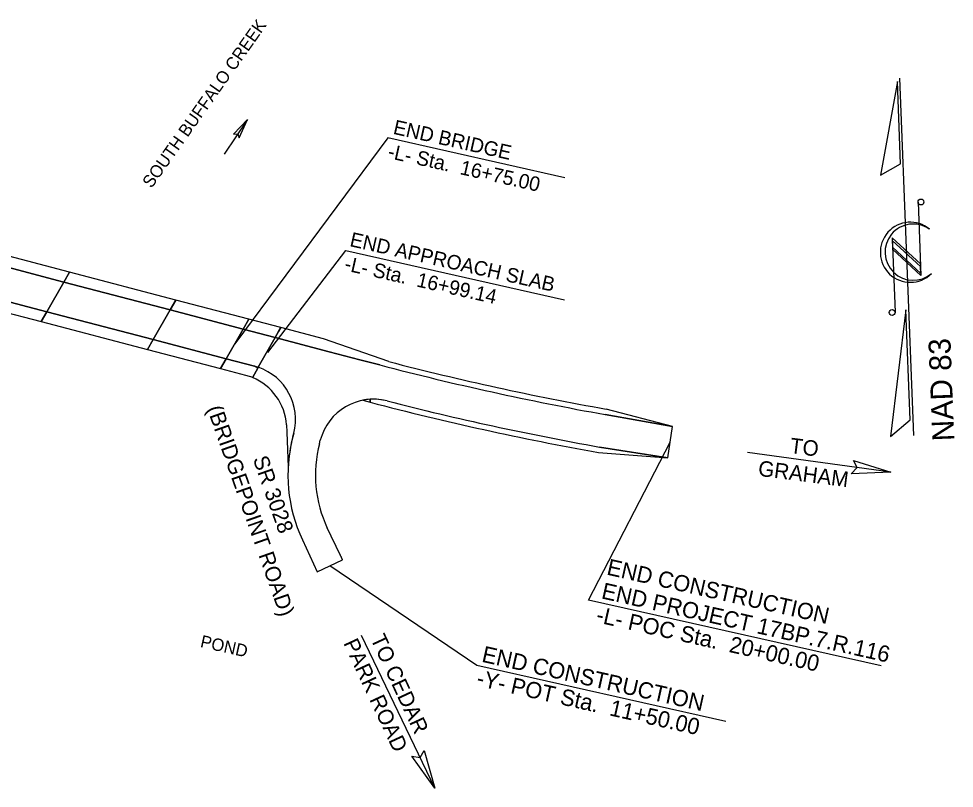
# Model space of a CAD drawing. Extents: x 1784499 to 1786147, y 841097 to 842538.
# Drawn here: x 1785466 to 1786147, y 841097 to 841656 of the extents above; entities that cross this region are included whole.
import ezdxf

# ---------------------------------------------------------------- set-up
doc = ezdxf.new("R2010")
doc.units = 0
for name, color, linetype in [('Exist Hydro Stream or Body of Water Text', 7, 'Continuous'), ('Exist Roads EOP Text', 7, 'Continuous'), ('Prop DSN Text', 7, 'Continuous'), ('Prop Horizontal Alignment Station Label', 7, 'Continuous'), ('Prop Leader Line Medium', 7, 'Continuous'), ('Prop Shade Light', 7, 'Continuous'), ('Prop Terminator CELL', 7, 'Continuous'), ('Sheet North Arrow CELL', 7, 'Continuous')]:
    doc.layers.add(name, color=color, linetype=linetype)

msp = doc.modelspace()

# ---------------------------------------------------------------- linework, layer by layer
at = {"layer": 'Prop DSN Text'}
for p, q in [((1785735.02, 841569.71), (1785623.67, 841419.93)), ((1785863.87, 841540.82), (1785735.02, 841569.71)), ((1785647.85, 841413.6), (1785704.42, 841487.83)), ((1785704.42, 841487.83), (1785863.65, 841452.12))]:
    msp.add_line(p, q, dxfattribs=at)
at = {"layer": 'Prop Horizontal Alignment Station Label'}
for p, q in [((1785881.09, 841233.67), (1785940.53, 841348.54)), ((1785799.79, 841186.08), (1785692.94, 841258.65)), ((1786094.14, 841185.89), (1785881.09, 841233.67)), ((1785980.91, 841145.46), (1785799.79, 841186.08))]:
    msp.add_line(p, q, dxfattribs=at)
at = {"layer": 'Prop Leader Line Medium'}
for p, q in [((1785632.85, 841583.2), (1785616.01, 841557.96)), ((1786101.01, 841326.66), (1785996.85, 841340.92)), ((1785769.21, 841096.81), (1785715.99, 841207.96))]:
    msp.add_line(p, q, dxfattribs=at)
at = {"layer": 'Prop Shade Light'}
for p, q in [((1785503.33, 841472.15), (1785450.13, 841486.09)), ((1785499.23, 841464.95), (1785446.03, 841478.89)), ((1785446.03, 841478.89), (1785499.23, 841464.95)), ((1785499.23, 841464.95), (1785503.33, 841472.15)), ((1785503.33, 841472.15), (1785499.23, 841464.95)), ((1785580.72, 841451.87), (1785503.33, 841472.15)), ((1785486.92, 841443.36), (1785499.23, 841464.95)), ((1785499.23, 841464.95), (1785486.92, 841443.36)), ((1785576.62, 841444.67), (1785499.23, 841464.95)), ((1785499.23, 841464.95), (1785576.62, 841444.67)), ((1785433.72, 841457.31), (1785486.92, 841443.36)), ((1785486.92, 841443.36), (1785433.72, 841457.31)), ((1785576.62, 841444.67), (1785580.72, 841451.87)), ((1785580.72, 841451.87), (1785576.62, 841444.67)), ((1785633.92, 841437.92), (1785580.72, 841451.87)), ((1785429.62, 841450.11), (1785482.82, 841436.17)), ((1785482.82, 841436.17), (1785486.92, 841443.36)), ((1785486.92, 841443.36), (1785482.82, 841436.17)), ((1785486.92, 841443.36), (1785564.31, 841423.08)), ((1785564.31, 841423.08), (1785486.92, 841443.36)), ((1785564.31, 841423.08), (1785576.62, 841444.67)), ((1785576.62, 841444.67), (1785564.31, 841423.08)), ((1785576.62, 841444.67), (1785629.82, 841430.73)), ((1785629.82, 841430.73), (1785576.62, 841444.67)), ((1785629.82, 841430.73), (1785633.92, 841437.92)), ((1785633.92, 841437.92), (1785629.82, 841430.73)), ((1785657.27, 841431.8), (1785633.92, 841437.92)), ((1785482.82, 841436.17), (1785560.21, 841415.89)), ((1785617.51, 841409.14), (1785629.82, 841430.73)), ((1785629.82, 841430.73), (1785617.51, 841409.14)), ((1785653.17, 841424.61), (1785629.82, 841430.73)), ((1785629.82, 841430.73), (1785653.17, 841424.61)), ((1785655.6, 841428.87), (1785657.27, 841431.8)), ((1785657.27, 841431.8), (1785655.6, 841428.87)), ((1785688.33, 841423.66), (1785657.27, 841431.8)), ((1785560.21, 841415.89), (1785564.31, 841423.08)), ((1785564.31, 841423.08), (1785560.21, 841415.89)), ((1785564.31, 841423.08), (1785617.51, 841409.14)), ((1785617.51, 841409.14), (1785564.31, 841423.08)), ((1785640.81, 841402.93), (1785653.17, 841424.61)), ((1785653.17, 841424.61), (1785640.81, 841402.93)), ((1785653.17, 841424.61), (1785655.6, 841428.87)), ((1785655.6, 841428.87), (1785653.17, 841424.61)), ((1785692.49, 841414.3), (1785653.17, 841424.61)), ((1785653.17, 841424.61), (1785692.49, 841414.3)), ((1785735.74, 841407.11), (1785688.33, 841423.66)), ((1785560.21, 841415.89), (1785613.41, 841401.95)), ((1785714.74, 841408.47), (1785692.49, 841414.3)), ((1785692.49, 841414.3), (1785714.74, 841408.47)), ((1785613.41, 841401.95), (1785617.51, 841409.14)), ((1785617.51, 841409.14), (1785613.41, 841401.95)), ((1785638.04, 841403.76), (1785617.51, 841409.14)), ((1785617.51, 841409.14), (1785638.04, 841403.76)), ((1785729.33, 841404.65), (1785714.74, 841408.47)), ((1785714.74, 841408.47), (1785729.33, 841404.65)), ((1785613.41, 841401.95), (1785631.55, 841397.19)), ((1785631.55, 841397.19), (1785636.76, 841395.83)), ((1785716.83, 841378.98), (1785722.23, 841377.57)), ((1785942.29, 841359.92), (1785893.32, 841368.57)), ((1785893.32, 841368.57), (1785942.29, 841359.92)), ((1785942.29, 841359.92), (1785894.03, 841372.51)), ((1785661.33, 841361.08), (1785661.67, 841355.83)), ((1785661.67, 841355.83), (1785662.5, 841330.27)), ((1785666.59, 841354.93), (1785665.95, 841352.47)), ((1785665.95, 841352.47), (1785666.59, 841354.93)), ((1785938.76, 841337.04), (1785942.29, 841359.92)), ((1785685.29, 841347.4), (1785685.95, 841349.89)), ((1785889.1, 841344.94), (1785938.76, 841337.04)), ((1785938.76, 841337.04), (1785889.1, 841344.94)), ((1785888.4, 841341.01), (1785938.76, 841337.04)), ((1785691.27, 841285.52), (1785691.02, 841286.06)), ((1785672.94, 841277.5), (1785683.59, 841254.22)), ((1785683.59, 841254.22), (1785702.17, 841263.02))]:
    msp.add_line(p, q, dxfattribs=at)
for points in [[(1785640.81, 841402.93), (1785640.49, 841402.36), (1785639.25, 841400.18), (1785636.76, 841395.83)], [(1785640.49, 841402.36), (1785638.04, 841403.76)], [(1785636.76, 841395.83), (1785636.63, 841395.49)], [(1785636.76, 841395.83), (1785639.25, 841400.18), (1785640.49, 841402.36)], [(1785722.1, 841379.67), (1785722.23, 841377.56)], [(1785722.23, 841377.57), (1785722.1, 841379.67)]]:
    msp.add_lwpolyline(points, dxfattribs=at)
for centre, radius, start, end in [((1785627.9, 841365.07), 40, 71.16248, 75.31501), ((1785627.9, 841365.07), 40, 345.31501, 71.16248), ((1785627.9, 841365.07), 40, 345.31501, 71.16248), ((1786264.98, 843448.63), 2113, 255.31501, 259.86941), ((1786264.98, 843448.63), 2113, 255.31501, 259.86941), ((1786264.98, 843448.63), 2109, 255.46645, 259.86941), ((1785621.41, 841358.5), 40, 3.69528, 67.64057), ((1785724.64, 841339.75), 40, 75.6286, 165.31501), ((1785724.64, 841339.75), 40, 93.64367, 101.25487), ((1785724.64, 841339.75), 40, 75.6286, 93.64367), ((1786264.98, 843448.63), 2141, 255.31501, 259.86941), ((1786264.98, 843448.63), 2137, 255.6286, 259.86941), ((1786264.98, 843448.63), 2137, 255.6286, 259.86941), ((1785772.35, 841324.59), 110, 165.31501, 205.34637), ((1785772.35, 841324.59), 110, 165.31501, 177.03762), ((1785772.35, 841324.59), 90, 165.31501, 205.34637)]:
    msp.add_arc(centre, radius, start, end, dxfattribs=at)
for points in [[(1785694.9, 841278.02), (1785694.87, 841278.09), (1785694.84, 841278.16), (1785694.8, 841278.23), (1785694.76, 841278.33), (1785694.71, 841278.43), (1785694.66, 841278.53), (1785694.61, 841278.63), (1785694.56, 841278.73), (1785694.51, 841278.83), (1785694.46, 841278.94), (1785694.41, 841279.04), (1785694.36, 841279.14), (1785694.31, 841279.24), (1785694.26, 841279.34), (1785694.22, 841279.44), (1785694.17, 841279.54), (1785694.12, 841279.65), (1785694.07, 841279.75), (1785694.02, 841279.85), (1785693.97, 841279.95), (1785693.92, 841280.05), (1785693.87, 841280.15), (1785693.82, 841280.25), (1785693.77, 841280.35), (1785693.72, 841280.46), (1785693.68, 841280.56), (1785693.63, 841280.66), (1785693.58, 841280.76), (1785693.53, 841280.86), (1785693.48, 841280.96), (1785693.43, 841281.06), (1785693.38, 841281.17), (1785693.33, 841281.27), (1785693.28, 841281.37), (1785693.23, 841281.47), (1785693.18, 841281.57), (1785693.14, 841281.67), (1785693.09, 841281.77), (1785693.04, 841281.88), (1785692.99, 841281.98), (1785692.94, 841282.08), (1785692.89, 841282.18), (1785692.84, 841282.28), (1785692.79, 841282.38), (1785692.74, 841282.48), (1785692.69, 841282.58), (1785692.64, 841282.69), (1785692.6, 841282.79), (1785692.55, 841282.89), (1785692.5, 841282.99), (1785692.45, 841283.09), (1785692.4, 841283.19), (1785692.35, 841283.29), (1785692.3, 841283.4), (1785692.25, 841283.5), (1785692.2, 841283.6), (1785692.15, 841283.7), (1785692.1, 841283.8), (1785692.06, 841283.9), (1785692.01, 841284), (1785691.96, 841284.1), (1785691.91, 841284.21), (1785691.86, 841284.31), (1785691.81, 841284.41), (1785691.76, 841284.51), (1785691.71, 841284.61), (1785691.66, 841284.71), (1785691.61, 841284.81), (1785691.56, 841284.92), (1785691.52, 841285.02), (1785691.47, 841285.12), (1785691.42, 841285.22), (1785691.37, 841285.32), (1785691.32, 841285.42), (1785691.27, 841285.52)], [(1785698.53, 841270.52), (1785698.52, 841270.56), (1785698.5, 841270.59), (1785698.49, 841270.62), (1785698.44, 841270.73), (1785698.39, 841270.83), (1785698.34, 841270.93), (1785698.29, 841271.03), (1785698.24, 841271.13), (1785698.19, 841271.23), (1785698.14, 841271.33), (1785698.09, 841271.44), (1785698.04, 841271.54), (1785698, 841271.64), (1785697.95, 841271.74), (1785697.9, 841271.84), (1785697.85, 841271.94), (1785697.8, 841272.04), (1785697.75, 841272.14), (1785697.7, 841272.25), (1785697.65, 841272.35), (1785697.6, 841272.45), (1785697.55, 841272.55), (1785697.5, 841272.65), (1785697.46, 841272.75), (1785697.41, 841272.85), (1785697.36, 841272.96), (1785697.31, 841273.06), (1785697.26, 841273.16), (1785697.21, 841273.26), (1785697.16, 841273.36), (1785697.11, 841273.46), (1785697.06, 841273.56), (1785697.01, 841273.67), (1785696.96, 841273.77), (1785696.92, 841273.87), (1785696.87, 841273.97), (1785696.82, 841274.07), (1785696.77, 841274.17), (1785696.72, 841274.27), (1785696.67, 841274.37), (1785696.62, 841274.48), (1785696.57, 841274.58), (1785696.52, 841274.68), (1785696.47, 841274.78), (1785696.42, 841274.88), (1785696.38, 841274.98), (1785696.33, 841275.08), (1785696.28, 841275.19), (1785696.23, 841275.29), (1785696.18, 841275.39), (1785696.13, 841275.49), (1785696.08, 841275.59), (1785696.03, 841275.69), (1785695.98, 841275.79), (1785695.93, 841275.89), (1785695.88, 841276), (1785695.84, 841276.1), (1785695.79, 841276.2), (1785695.74, 841276.3), (1785695.69, 841276.4), (1785695.64, 841276.5), (1785695.59, 841276.6), (1785695.54, 841276.71), (1785695.49, 841276.81), (1785695.44, 841276.91), (1785695.39, 841277.01), (1785695.34, 841277.11), (1785695.3, 841277.21), (1785695.25, 841277.31), (1785695.2, 841277.42), (1785695.15, 841277.52), (1785695.1, 841277.62), (1785695.05, 841277.72), (1785695, 841277.82), (1785694.95, 841277.92), (1785694.94, 841277.96), (1785694.92, 841277.99), (1785694.9, 841278.02)], [(1785702.17, 841263.02), (1785702.07, 841263.23), (1785701.97, 841263.43), (1785701.87, 841263.63), (1785701.82, 841263.73), (1785701.77, 841263.83), (1785701.73, 841263.93), (1785701.68, 841264.04), (1785701.63, 841264.14), (1785701.58, 841264.24), (1785701.53, 841264.34), (1785701.48, 841264.44), (1785701.43, 841264.54), (1785701.38, 841264.64), (1785701.33, 841264.75), (1785701.28, 841264.85), (1785701.23, 841264.95), (1785701.19, 841265.05), (1785701.14, 841265.15), (1785701.09, 841265.25), (1785701.04, 841265.35), (1785700.99, 841265.46), (1785700.94, 841265.56), (1785700.89, 841265.66), (1785700.84, 841265.76), (1785700.79, 841265.86), (1785700.74, 841265.96), (1785700.69, 841266.06), (1785700.65, 841266.16), (1785700.6, 841266.27), (1785700.55, 841266.37), (1785700.5, 841266.47), (1785700.45, 841266.57), (1785700.4, 841266.67), (1785700.35, 841266.77), (1785700.3, 841266.87), (1785700.25, 841266.98), (1785700.2, 841267.08), (1785700.15, 841267.18), (1785700.11, 841267.28), (1785700.06, 841267.38), (1785700.01, 841267.48), (1785699.96, 841267.58), (1785699.91, 841267.69), (1785699.86, 841267.79), (1785699.81, 841267.89), (1785699.76, 841267.99), (1785699.71, 841268.09), (1785699.66, 841268.19), (1785699.61, 841268.29), (1785699.57, 841268.39), (1785699.52, 841268.5), (1785699.47, 841268.6), (1785699.42, 841268.7), (1785699.37, 841268.8), (1785699.32, 841268.9), (1785699.27, 841269), (1785699.22, 841269.1), (1785699.17, 841269.21), (1785699.12, 841269.31), (1785699.07, 841269.41), (1785699.03, 841269.51), (1785698.98, 841269.61), (1785698.93, 841269.71), (1785698.88, 841269.81), (1785698.83, 841269.91), (1785698.78, 841270.02), (1785698.73, 841270.12), (1785698.68, 841270.22), (1785698.63, 841270.32), (1785698.6, 841270.39), (1785698.57, 841270.46), (1785698.53, 841270.52)]]:
    msp.add_open_spline(points, degree=3, dxfattribs=at)
at = {"layer": 'Prop Terminator CELL'}
for points in [[(1785626.92, 841569.84), (1785632.85, 841583.2), (1785622.68, 841572.57), (1785625.83, 841572.68)], [(1786073.8, 841335.27), (1786101.01, 841326.66), (1786072.31, 841325.54), (1786076.55, 841330.01)], [(1785761.43, 841124.27), (1785769.21, 841096.81), (1785752.48, 841120.16), (1785758.55, 841119.07)]]:
    msp.add_lwpolyline(points, close=True, dxfattribs=at)
at = {"layer": 'Sheet North Arrow CELL'}
for p, q in [((1786117.75, 841353.32), (1786107.51, 841613.12)), ((1786120.87, 841523.09), (1786122.97, 841469.78)), ((1786129, 841503.52), (1786129.29, 841503.33)), ((1786122.64, 841478.09), (1786101.99, 841497.17)), ((1786101.99, 841497.17), (1786104.13, 841442.97)), ((1786122.72, 841476.13), (1786102.07, 841495.21)), ((1786102.07, 841495.21), (1786102.26, 841490.34)), ((1786122.91, 841471.25), (1786102.26, 841490.34)), ((1786102.26, 841490.34), (1786122.91, 841471.25)), ((1786122.97, 841469.78), (1786102.32, 841488.86)), ((1786122.91, 841471.25), (1786122.72, 841476.13))]:
    msp.add_line(p, q, dxfattribs=at)
for points in [[(1786105.81, 841610.77), (1786093.63, 841542.72), (1786108.17, 841550.82)], [(1786112.02, 841444.76), (1786100.92, 841352.66), (1786115.17, 841364.83)]]:
    msp.add_lwpolyline(points, close=True, dxfattribs=at)
for centre in [(1786122.99, 841523.14), (1786102.01, 841442.81)]:
    msp.add_circle(centre, 2.12, dxfattribs=at)
for centre, radius, start, end in [((1786115.26, 841486.58), 21.84, 50.09518, 314.64921), ((1786117.37, 841486.67), 20.47, 55.3502, 310.88386)]:
    msp.add_arc(centre, radius, start, end, dxfattribs=at)

# ---------------------------------------------------------------- texts
at = {"layer": 'Exist Hydro Stream or Body of Water Text'}
for s, rotation, p in [('SOUTH BUFFALO CREEK', 54.78534, (1785563.11, 841532.63)), ('POND', 347.35991, (1785598.07, 841199.56))]:
    msp.add_text(s, height=9, rotation=rotation, dxfattribs=at).set_placement(p)
at = {"layer": 'Exist Roads EOP Text'}
for s, rotation, p in [('(BRIDGEPOINT ROAD)', 289.36703, (1785603.4, 841372.98)), ('TO ', 352.72078, (1786027.14, 841340.61)), ('SR 3028 ', 289.36703, (1785636.72, 841336.34)), ('GRAHAM', 352.72078, (1786004.05, 841324.11)), ('PARK ROAD', 294.8886, (1785702.49, 841202.42)), ('TO CEDAR', 294.8886, (1785722.24, 841205.68))]:
    msp.add_text(s, height=11.25, rotation=rotation, dxfattribs=at).set_placement(p)
at = {"layer": 'Prop DSN Text'}
for s, p in [('END BRIDGE', (1785738.4, 841572.8)), ('-L- Sta.  16+75.00', (1785734.46, 841555.23)), ('END APPROACH SLAB', (1785706.81, 841491.13)), ('-L- Sta.  16+99.14', (1785702.87, 841473.57))]:
    msp.add_text(s, height=10.5, rotation=347.3599, dxfattribs=at).set_placement(p)
at = {"layer": 'Prop Horizontal Alignment Station Label'}
for s, p in [('END CONSTRUCTION', (1785893.74, 841252.28)), ('END PROJECT 17BP.7.R.116', (1785889.87, 841234.99)), ('-L- POC Sta.  20+00.00', (1785885.99, 841217.71)), ('END CONSTRUCTION', (1785802.8, 841188.91)), ('-Y- POT Sta.  11+50.00', (1785798.93, 841171.62))]:
    msp.add_text(s, height=11.8125, rotation=347.3599, dxfattribs=at).set_placement(p)
at = {"layer": 'Sheet North Arrow CELL'}
msp.add_text('         NAD 83', height=16.0001, rotation=92.25516, dxfattribs=at).set_placement((1786149.42, 841296.05))

doc.saveas('drawing.dxf')
